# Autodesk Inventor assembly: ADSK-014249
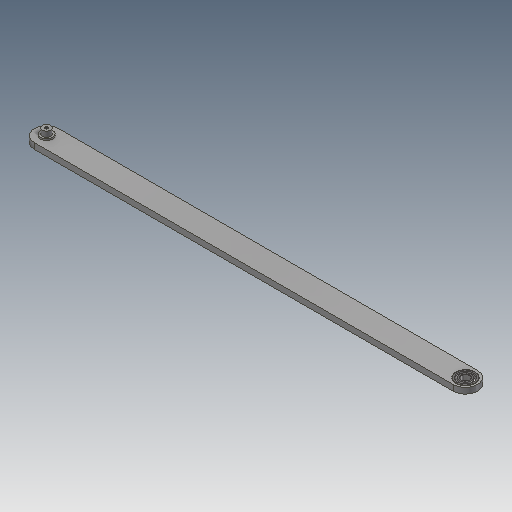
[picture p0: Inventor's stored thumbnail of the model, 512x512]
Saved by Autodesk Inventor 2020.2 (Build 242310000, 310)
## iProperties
Created: 2019-10
Part Number: ADSK-014249
Document SubType Name: Assembly
Designer: lutzd
Mass: 4210.14 g
Surface Area: 1203.82 cm^2
Volume: 536.997 cm^3
Density: 7.84015 g/cm^3
VLDS_Profile: Default Assembly
VLDS_TimeStamp: 2016-07-29
VLDS_FailCnt: 0
VLDS_AcceptCnt: 0
Dimensions: 50x26x911,5 mm
Mass: 4,21 kg
DocNumber: ADSK-014249
Folder: 01 - Themengebiete\Simplification\01 - Packaging machine\
VDS_Category: 3D Komponenten
VDS_NumSchm: Autodesk
Title: connection
Author: lutzd
Revision Number: -
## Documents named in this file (4)
- D:\07 - DEMODATEN\OTX 2019 - Dataset - UPDATE - Dez2019\Designs\07-Packing machine\ADSK-014249.iam
- D:\07 - DEMODATEN\OTX 2019 - Dataset - UPDATE - Dez2019\Designs\07-Packing machine\Parts\ADSK-014247.ipt
- D:\07 - DEMODATEN\OTX 2019 - Dataset - UPDATE - Dez2019\Designs\07-Packing machine\Parts\ADSK-014248.ipt
- D:\07 - DEMODATEN\OTX 2019 - Dataset - UPDATE - Dez2019\Content Center Files\de-DE\DIN 625 SKF(5)\DIN 625 SKF - SKF 6203-2RSH.ipt
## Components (3 placed, 3 different names)
1. ADSK-014247:1 — Einfügen:1, Passend:1, Fluchtend:1
2. ADSK-014248:1 — Einfügen:1
3. DIN 625 SKF- beidseitig abgedichtet SKF 6203-2RSH:1 — Passend:1, Fluchtend:1
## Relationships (3: Insert 1, Mate 1, Flush 1)
- Einfügen:1 [Insert]: ADSK-014247:1 ↔ ADSK-014248:1
- Passend:1 [Mate]: ADSK-014247:1 ↔ DIN 625 SKF- beidseitig abgedichtet SKF 6203-2RSH:1
- Fluchtend:1 [Flush]: ADSK-014247:1 ↔ DIN 625 SKF- beidseitig abgedichtet SKF 6203-2RSH:1
